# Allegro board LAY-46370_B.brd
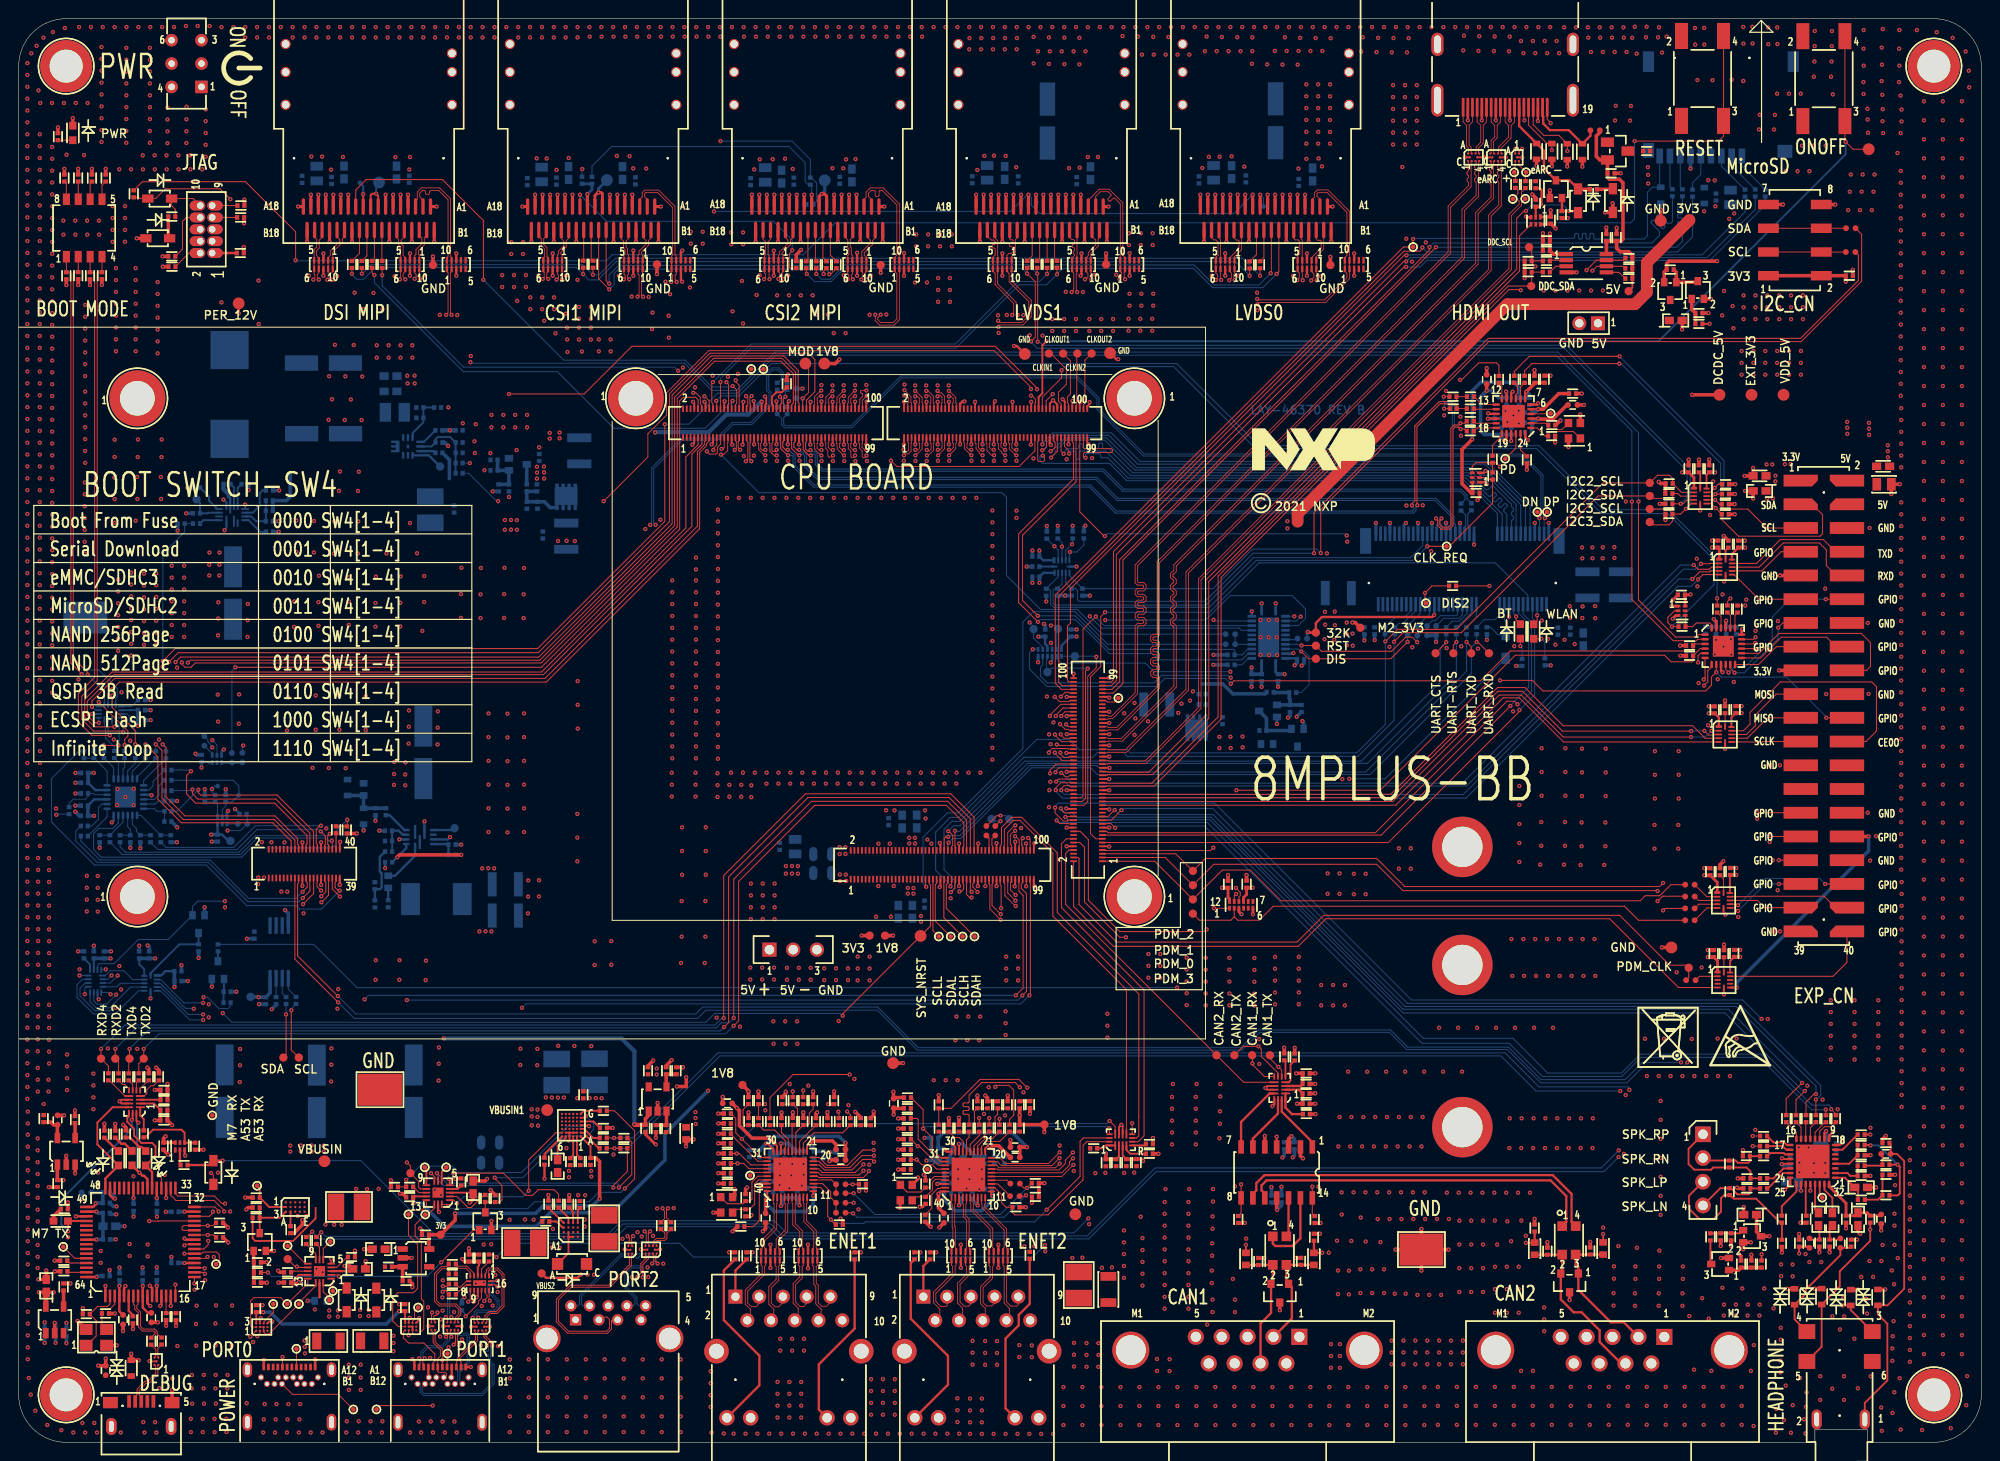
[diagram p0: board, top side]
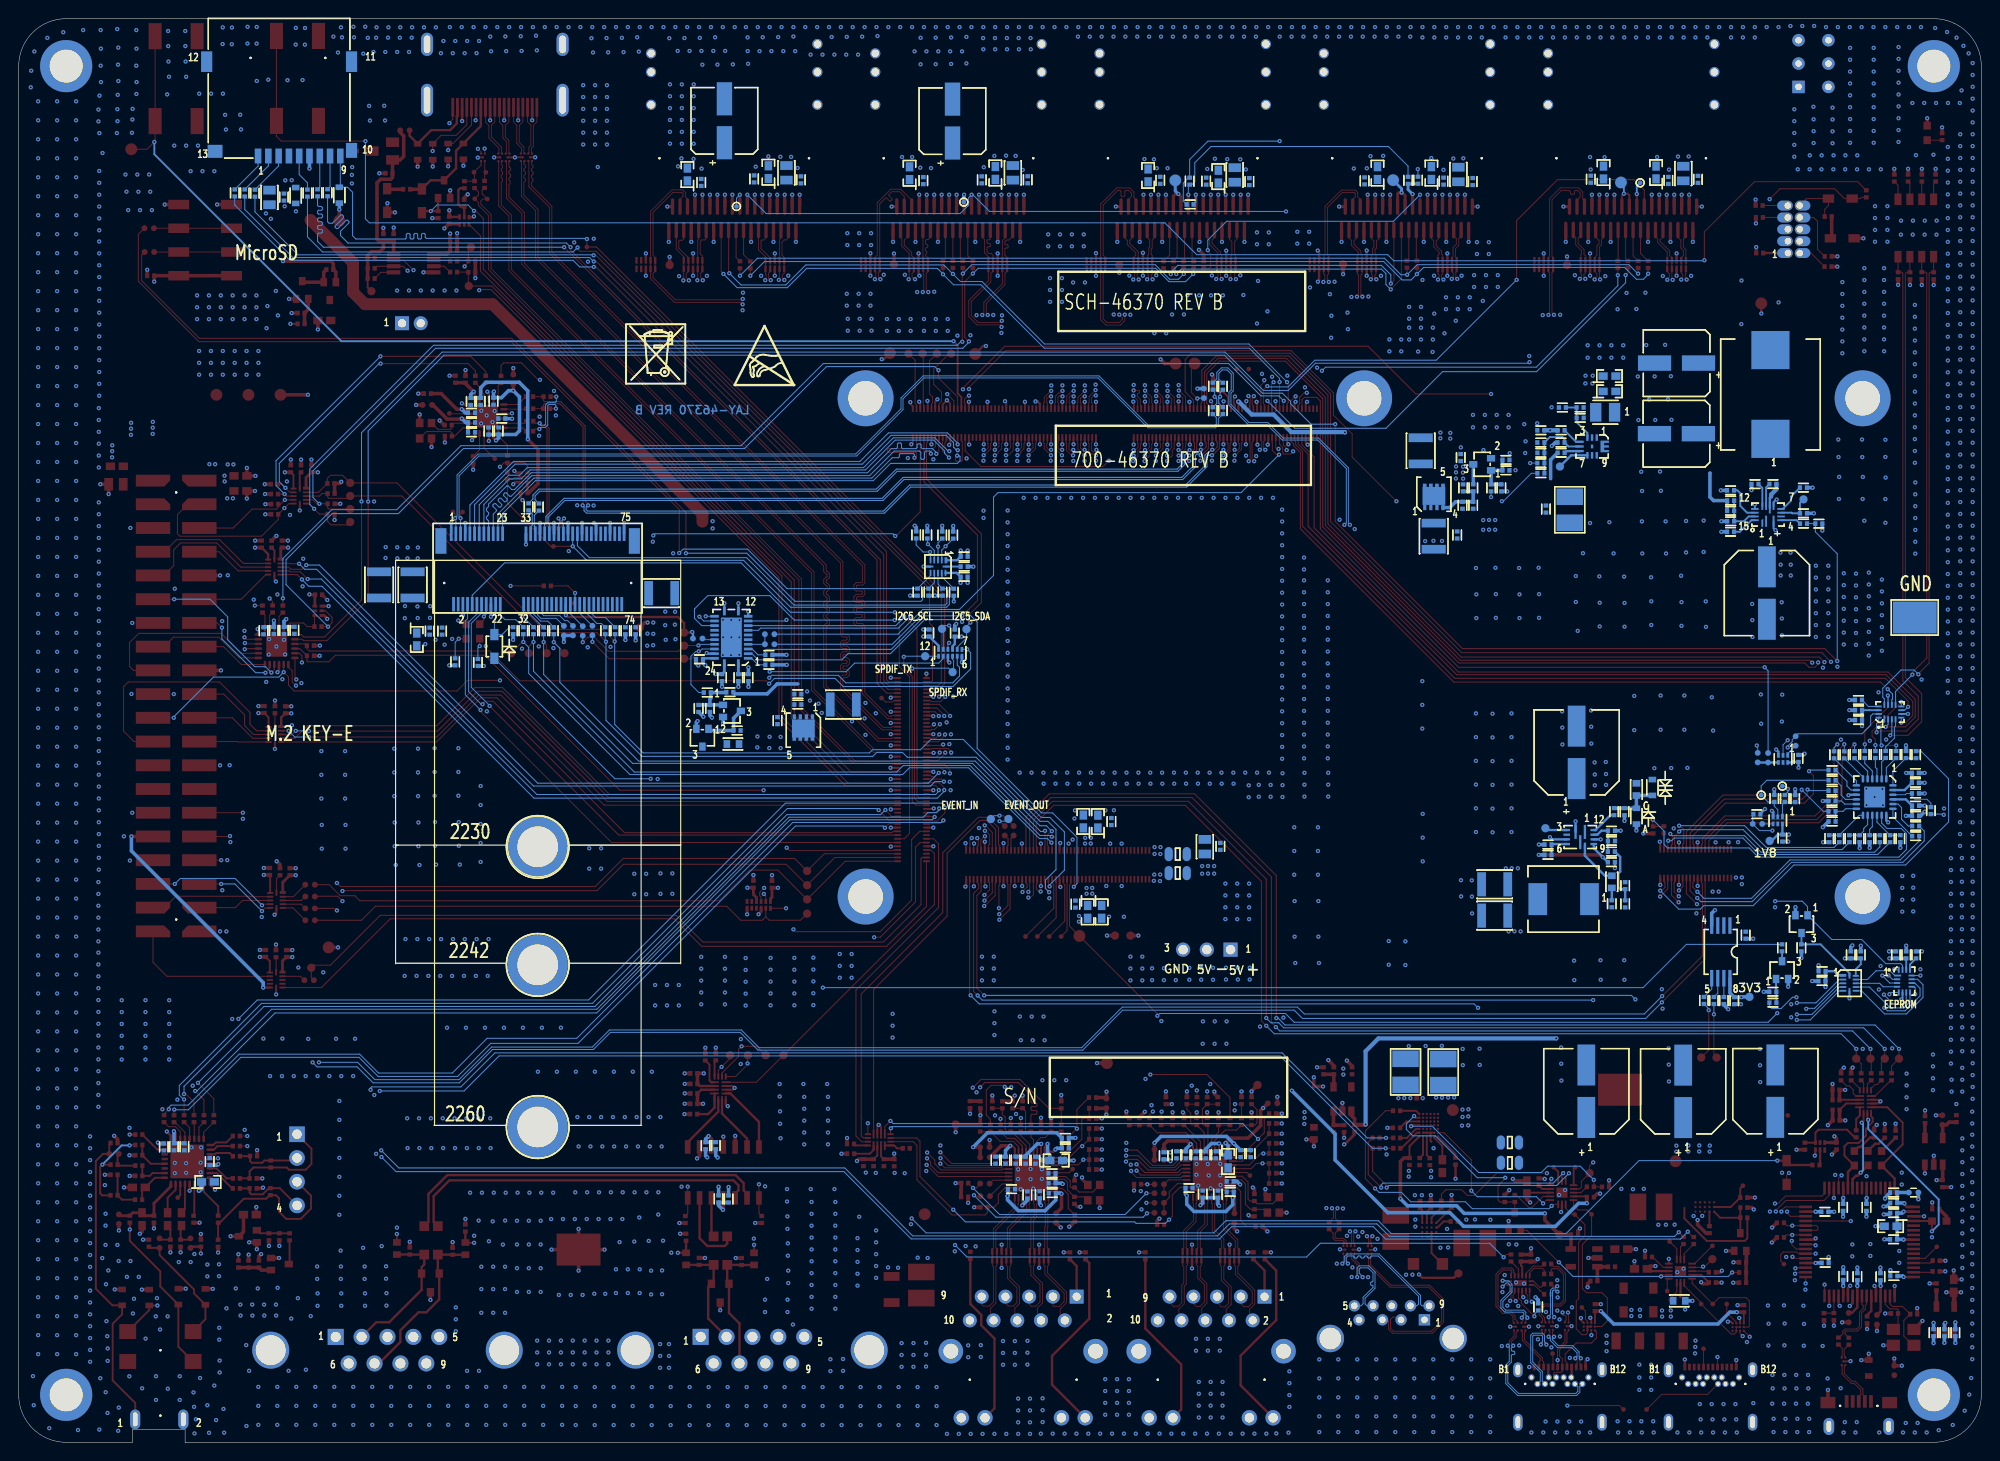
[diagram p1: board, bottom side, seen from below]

Outline 210 x 152.4 mm; copper layers: TOP, L2_GND1, L3_IN1, L4_POWER_1, L5_POWER_2, L6_IN2, L7_GND2, BOTTOM. Coordinates in mm from the lower left corner of the outline.
Outline path: 0,147.32 arc(1.49,150.91) 5.08,152.4 204.92,152.4 arc(208.51,150.91) 210,147.32 210,5.08 arc(208.51,1.49) 204.92,0 197.81,0 197.81,1.35 192.2,1.35 192.19,1.35 192.19,0.01 192.18,0 5.08,0 arc(1.49,1.49) 0,5.08 0,147.32

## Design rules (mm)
constraint set DEFAULT: min track width 0.109
net group AUD_PWR_EN: nets AUD_PWR_EN N108752409
net group DIFFPAIR0: nets USB_DBG_DN USB_DBG_DP
net group DIFFPAIR25: nets USB1_TXN USB1_TXP
net group DIFFPAIR26: nets USB1_RXN USB1_RXP
net group DIFFPAIR27: nets USB2_TXN USB2_TXP
net group DIFFPAIR28: nets USB2_RXN USB2_RXP
net group DIFFPAIR30: nets ST_FT_USB_DN ST_FT_USB_DP
net group DIFFPAIR31: nets FT_USB_DN FT_USB_DP
net group DIFFPAIR32: nets USB_HOST_DN USB_HOST_DP
net group DIFFPAIR33: nets USB_HOST_RXN USB_HOST_RXP
net group DIFFPAIR34: nets USB_HOST_TXN USB_HOST_TXP
net group DIFFPAIR35: nets USB1_DN_CN USB1_DP_CN
net group DIFFPAIR36: nets SSTXN2 SSTXP2
net group DIFFPAIR37: nets SSRXN2 SSRXP2
net group DIFFPAIR38: nets SSRXN1 SSRXP1
net group DIFFPAIR39: nets ETH1_TRX3_N ETH1_TRX3_P
net group DIFFPAIR40: nets ETH1_TRX2_N ETH1_TRX2_P
net group DIFFPAIR41: nets ETH1_TRX1_N ETH1_TRX1_P
net group DIFFPAIR42: nets ETH1_TRX0_N ETH1_TRX0_P
net group DIFFPAIR43: nets HDMI_TXN2_CN HDMI_TXP2_CN
net group DIFFPAIR44: nets HDMI_TXN1_CN HDMI_TXP1_CN
net group DIFFPAIR45: nets HDMI_TXN0_CN HDMI_TXP0_CN
net group DIFFPAIR46: nets HDMI_CLKN_CN HDMI_CLKP_CN
net group DIFFPAIR47: nets SS_RXN1 SS_RXP1
net group DIFFPAIR48: nets SS_RXN2 SS_RXP2
net group DIFFPAIR49: nets SS_TXN2 SS_TXP2
net group DIFFPAIR50: nets SS_TXN1 SS_TXP1
net group DIFFPAIR51: nets SSTXN1 SSTXP1
net group DIFFPAIR52: nets USB2_H_DN USB2_H_DP
net group DIFFPAIR53: nets USB2_H_TXN USB2_H_TXP
net group DIFFPAIR54: nets M2_USB_DN M2_USB_DP
net group DIFFPAIR55: nets EARC_N_HPD EARC_P_UTIL
net group DIFFPAIR56: nets CAN2H CAN2L
net group ENET1_MDIO: nets ENET1_MDIO ETH1_MDIO
net group ENET1_RD0: nets ENET1_RD0 ENET1_RXD0/RXDLY
net group ENET1_RD1: nets ENET1_RD1 ENET1_RXD1/TXDLY
net group ENET1_RD2: nets ENET1_RD2 ENET1_RXD2/PLLOFF
net group ENET1_RX_CTL: nets ENET1_RX_CTL ENET1_RXCTL/PHYAD2
net group ENET1_RXC: nets ENET1_RXC ENET1_RXC/PHYAD1
net group ETH1_MDC: nets ENET1_MDC ETH1_MDC
net group ETH_TRX0: nets ETH_TRX0_N ETH_TRX0_P
net group ETH_TRX1: nets ETH_TRX1_N ETH_TRX1_P
net group ETH_TRX2: nets ETH_TRX2_N ETH_TRX2_P
net group ETH_TRX3: nets ETH_TRX3_N ETH_TRX3_P
net group HP_MIC_P: nets HP_MIC_P N108750181
net group I2C2_SCL_3V3: nets I2C2_SCL_3V3 N104279466
net group I2C2_SDA_3V3: nets I2C2_SDA_3V3 N104279469
net group N108752359: nets N108752359 N108752379
net group PCIE_RX: nets PCIE_RXN PCIE_RXP
net group PCIE_TXN: nets N105095143 PCIE_TXN
net group PCIE_TXP: nets N105095140 PCIE_TXP
net group SPKOUTLN: nets SPK_LN SPKOUTLN
net group SPKOUTLP: nets SPK_LP SPKOUTLP
net group SPKOUTRN: nets SPK_RN SPKOUTRN
net group SPKOUTRP: nets SPK_RP SPKOUTRP
net group USB1_D: nets USB1_DN USB1_DP
net group USB2_D: nets USB2_DN USB2_DP
net group CAN1_H: nets CAN1_H CAN1_L N109066072
net group CAN2_H: nets CAN2_H CAN2_L N109088165
net group DSI: nets DSI_CKN DSI_CKP DSI_DN0 DSI_DN1 DSI_DN2 DSI_DN3 DSI_DP0 DSI_DP1 DSI_DP2 DSI_DP3
net group ETH1_DVDD3V3: nets ETH1_LED0/CFG_EXT
net group M-ENET1-TX: nets ENET1_TD0 ENET1_TD1 ENET1_TD2 ENET1_TD3 ENET1_TX_CTL ENET1_TXC
net group M-ENET-RX: nets ENET_RD0 ENET_RD1 ENET_RD2 ENET_RD3 ENET_RX_CTL ENET_RXC
net group M-ENET-TX: nets ENET_TD0 ENET_TD1 ENET_TD2 ENET_TD3 ENET_TX_CTL ENET_TXC
net group M-ENT1-RX: nets ENET1_RD3
net group M-HDMI: nets HDMI_TXCN HDMI_TXCP HDMI_TXN0 HDMI_TXN1 HDMI_TXN2 HDMI_TXP0 HDMI_TXP1 HDMI_TXP2
net group M-M2-SD: nets M2_SD_CLK M2_SD_CMD M2_SD_DATA0 M2_SD_DATA1 M2_SD_DATA2 M2_SD_DATA3 M2_SD_NRST M2_SD_WAKE_HOST
net group M-SD2: nets SD2_CLK SD2_CMD SD2_DATA0 SD2_DATA1 SD2_DATA2 SD2_DATA3
net group NCS_CLK: nets M2_PCM_CLK
net group NCS_POWER_PH: nets ILIM_5V_VBUS1 N101995244 N101995353 VCC_3V6 VLDO1_3V3 VTREF
net group PCIE_REQ: nets N101995643 N101995645 PCIE_REQ
net group REF_CLKN_CN: nets N101995453 PCIE_CLKN REF_CLKN_CN
net group REF_CLKP_CN: nets N101995404 N101995436 PCIE_CLKP REF_CLKP_CN

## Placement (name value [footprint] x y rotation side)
BH1  SMTSO-M25  [MH244-166T]  154.47 63.74 180 bottom
BH2  STANDOFF M2.5  [STANDOFF_CIRCLE_5P1-2P5MM_NSP]  66.04 111.76 0 top
BH3  STANDOFF M2.5  [STANDOFF_CIRCLE_5P1-2P5MM_NSP]  119.38 58.42 0 top
BH4  STANDOFF M2.5  [STANDOFF_CIRCLE_5P1-2P5MM_NSP]  119.38 111.76 0 top
BH5  .635" LONG  [SPACER_139T]  5.08 5.08 0 top
BH6  .635" LONG  [SPACER_139T]  204.92 147.32 0 top
BH7  .635" LONG  [SPACER_139T]  204.92 5.08 0 top
BH8  .635" LONG  [SPACER_139T]  5.08 147.32 0 top
BH9  SMTSO-M25  [MH244-166T]  154.47 51.1 180 bottom
BH10  SMTSO-M25  [MH244-166T]  154.47 33.74 180 bottom
BH11  STANDOFF M2.5  [STANDOFF_CIRCLE_5P1-2P5MM_NSP]  12.7 111.76 0 top
BH12  STANDOFF M2.5  [STANDOFF_CIRCLE_5P1-2P5MM_NSP]  12.7 58.42 0 top
C1  1.0UF  [0402_CC]  180.5 86.92 270 bottom
C2  0.1uF  [0402_CC]  181.61 86.91 270 bottom
C3  1.0UF  [0402_CC]  182.7 86.91 270 bottom
C4  0.1uF  [0402_CC]  183.8 86.88 270 bottom
C5  0.1uF  [0402_CC]  177.91 90.73 180 top
C6  1.0UF  [0402_CC]  131.92 81.86 270 bottom
C7  0.1uF  [0402_CC]  132.99 81.86 270 bottom
C8  1.0UF  [0402_CC]  134.75 81.86 270 bottom
C9  0.1uF  [0402_CC]  137.16 83.83 0 bottom
C10  0.1uF  [0402_CC]  178.68 104.22 90 top
C11  0.1uF  [0402_CC]  180.88 104.22 90 top
C12  0.1uF  [0402_CC]  108.84 94.83 180 bottom
C13  0.1uF  [0402_CC]  108.84 92.65 180 bottom
C14  1.0UF  [0402_CC]  86.12 30.77 270 bottom
C15  4.7uF  [CC0603]  185.26 24.37 180 top
C16  0.1uF  [0402_CC]  81.43 63.79 90 bottom
C17  22uF  [0805_CC]  83.08 63.76 90 bottom
C18  0.1uF  [0402_CC]  93.08 66.45 90 bottom
C19  22uF  [CC0603]  96.09 66.46 90 bottom
C20  22uF  [CC0603]  94.53 66.45 90 bottom
C21  0.1uF  [0402_CC]  96.93 57.61 270 bottom
C22  22uF  [CC0603]  94.12 56.78 270 bottom
C23  22uF  [CC0603]  95.62 56.78 270 bottom
C24  4.7uF  [CC1210]  35.34 25.2 0 top
C25  100uF  [CCE8P3X8P3]  31.9 37.57 90 bottom
C26  100uF  [CCE8P3X8P3]  22.04 37.59 90 bottom
C27  0.1uF  [0402_CC]  25.41 14.31 90 top
C29  2.2uF  [0402_CC]  35.61 19.84 180 top
C30  4.7uF  [CC0603]  36.43 18.56 0 top
C31  0.1uF  [0402_CC]  28.78 17.1 0 top
C32  0.1uF  [0402_CC]  67.34 39.78 90 top
C33  0.1uF  [0402_CC]  109.84 86.63 90 bottom
C34  1uF  [CC0603]  38.52 20.68 180 top
C35  2.2uF  [0402_CC]  43.53 22.23 180 top
C36  4.7uF  [CC1210]  57.57 39.63 90 bottom
C37  0.1uF  [0402_CC]  112.56 86.64 90 bottom
C40  100uF  [CCE8P3X8P3]  42.27 37.58 90 bottom
C41  47UF  [CC1210]  61.61 39.66 90 bottom
C42  0.1uF  [0402_CC]  60.42 37.2 90 top
C43  0.01UF  [0402_CC]  56.26 30.1 270 top
C44  1000pF  [0402_CC]  59.01 30.05 270 top
C45  0.1uF  [0402_CC]  41.34 14.42 90 top
C46  0.1uF  [0402_CC]  61.19 30.06 270 top
C47  4.7uF  [CC0603]  57.67 29.56 270 top
C48  0.1uF  [0402_CC]  46.41 16.94 0 top
C50  0.1uF  [0402_CC]  46.4 15.84 0 top
C51  2.2uF  [0402_CC]  47.35 27.87 270 top
C52  0.1uF  [0402_CC]  46.4 19.09 0 top
C53  0.1uF  [0402_CC]  46.4 18.02 0 top
C54  4.7uF  [CC0603]  48.62 27.29 90 top
C55  0.22uF  [0402_CC]  49.26 19.72 90 top
C56  2.2uF  [0402_CC]  48.18 19.72 90 top
C57  0.1uF  [0402_CC]  41.83 26.24 0 top
C59  0.1uF  [0402_CC]  69.79 23.2 90 top
C60  0.1uF  [0402_CC]  68.72 23.19 90 top
C61  47UF  [CC1210]  54.2 21.34 0 top
C62  47UF  [CC1210]  62.66 22.9 90 top
C64  1000pF  [0402_CC]  60.05 25.45 90 top
C65  0.1uF  [0402_CC]  102.07 26.48 90 bottom
C66  0.1uF  [0402_CC]  100.75 26.5 90 bottom
C67  0.1uF  [0402_CC]  99.42 27.74 0 bottom
C68  1.0UF  [0402_CC]  99.4 26.67 0 bottom
C69  0.1uF  [0402_CC]  103.77 27.1 180 bottom
C70  4.7uF  [CC0603]  98.99 30.17 180 bottom
C71  0.1uF  [0402_CC]  101.21 30.2 270 bottom
C72  4.7uF  [0402_CC]  102.26 30.2 270 bottom
C73  0.1uF  [0402_CC]  103.33 30.21 270 bottom
C74  0.1uF  [0402_CC]  104.41 30.21 270 bottom
C75  0.22uF  [0402_CC]  97.51 19.96 90 top
C76  4.7uF  [0402_CC]  98.02 32.59 180 bottom
C77  0.1uF  [0402_CC]  98.01 31.48 180 bottom
C78  1000pF  [CC1210]  113.42 16.84 270 top
C79  22PF  [0402_CC]  97.02 27.65 90 top
C80  22PF  [0402_CC]  97.03 25.9 270 top
C81  22PF  [0402_CC]  98.44 36.13 90 top
C82  470PF  [0402_CC]  95.09 33.59 180 top
C83  470PF  [0402_CC]  95.09 30.26 180 top
C84  1.0UF  [0402_CC]  80.37 27.93 0 bottom
C85  0.1uF  [0402_CC]  83.31 26.57 90 bottom
C86  0.1uF  [0402_CC]  81.68 26.56 90 bottom
C87  1.0UF  [0402_CC]  80.37 26.81 0 bottom
C88  0.1uF  [0402_CC]  84.78 27.22 180 bottom
C89  4.7uF  [CC0603]  80.59 30.07 270 bottom
C90  0.1uF  [0402_CC]  81.91 30.78 270 bottom
C91  4.7uF  [0402_CC]  82.98 30.77 270 bottom
C92  0.1uF  [0402_CC]  84.05 30.77 270 bottom
C93  0.1uF  [0402_CC]  85.1 30.77 270 bottom
C94  0.22uF  [0402_CC]  77.88 19.96 90 top
C95  4.7uF  [0402_CC]  78.18 30.9 270 bottom
C96  0.1uF  [0402_CC]  79.26 30.9 270 bottom
C97  22PF  [0402_CC]  77.78 26.2 90 top
C98  22PF  [0402_CC]  77.77 24.57 270 top
C99  22PF  [0402_CC]  79.16 36.58 90 top
C100  470PF  [0402_CC]  75.83 32 180 top
C101  470PF  [0402_CC]  75.83 29.86 180 top
C102  1.0UF  [0402_CC]  161.63 111.42 270 bottom
C103  0.01UF  [0402_CC]  160.57 111.43 270 bottom
C104  1.0UF  [0402_CC]  158.31 109.59 0 bottom
C105  0.01UF  [0402_CC]  161.54 108.12 180 bottom
C106  0.01UF  [0402_CC]  161.54 109.17 180 bottom
C107  1.0UF  [0402_CC]  159.73 108.25 90 bottom
C108  0.01UF  [0402_CC]  159.2 111.46 270 bottom
C109  0.01UF  [0402_CC]  158.65 108.26 90 bottom
C110  18PF  [0402_CC]  164.03 107.71 0 top
C111  18PF  [0402_CC]  164.04 108.9 0 top
C112  0.1uF  [0402_CC]  143.99 86.88 270 bottom
C113  0.1uF  [0402_CC]  145.08 86.88 270 bottom
C114  0.1uF  [0402_CC]  164.7 86.84 270 bottom
C115  0.1uF  [0402_CC]  166.02 86.84 270 bottom
C116  10uF  [CC0603]  167.41 85.95 270 bottom
C117  100UF  [1210_CC]  171.44 91.79 90 bottom
C118  100UF  [1210_CC]  141.2 90.9 180 bottom
C119  100UF  [1210_CC]  167.86 91.79 90 bottom
C120  0.1uF  [0402_CC]  155.44 100.14 270 bottom
C121  0.1uF  [0402_CC]  154.33 100.12 270 bottom
C123  47uF  [0805_CC]  183.17 133.26 270 bottom
C124  0.1uF  [0402_CC]  181.62 133.3 270 bottom
C125  10uF  [CC0603]  64.61 135.87 90 bottom
C126  0.1uF  [0402_CC]  65.99 135.04 90 bottom
C127  22uF  [CC0603]  58.84 135.88 90 bottom
C128  0.1uF  [0402_CC]  57.54 135.01 90 bottom
C129  22uF  [0805_CC]  55.95 135.72 90 bottom
C130  0.1uF  [0402_CC]  54.42 134.96 90 bottom
C131  10uF  [CC0603]  89.15 135.62 90 bottom
C132  0.1uF  [0402_CC]  87.86 135.1 90 bottom
C133  22uF  [CC0603]  81.64 135.49 90 bottom
C134  0.1uF  [0402_CC]  82.94 135 90 bottom
C135  22uF  [0805_CC]  79.88 135.67 90 bottom
C136  0.1uF  [0402_CC]  78.32 134.96 90 bottom
C137  10uF  [CC0603]  40.43 135.93 90 bottom
C138  0.1uF  [0402_CC]  41.79 135.22 90 bottom
C139  22uF  [CC0603]  34.81 135.93 90 bottom
C140  0.1uF  [0402_CC]  33.48 135.08 90 bottom
C141  22uF  [0805_CC]  31.89 135.82 90 bottom
C142  0.1uF  [0402_CC]  30.32 135.2 90 bottom
C143  0.1uF  [0402_CC]  136.97 134.87 90 bottom
C144  22uF  [CC0603]  129.78 135.97 90 bottom
C145  0.1uF  [0402_CC]  126.3 135.15 90 bottom
C146  100uF  [CCE6P8X6P8]  134.49 141.47 90 bottom
C147  22uF  [CC0603]  114.68 135.86 90 bottom
C148  0.1uF  [0402_CC]  113.21 135.06 90 bottom
C149  0.1uF  [0402_CC]  106.95 135.15 90 bottom
C150  22uF  [0805_CC]  103.62 135.9 90 bottom
C151  100uF  [CCE6P8X6P8]  110.08 141.44 90 bottom
C152  10uF  [CC0603]  138.45 135.72 90 bottom
C153  0.1uF  [0402_CC]  131.31 135.25 90 bottom
C154  22uF  [0805_CC]  127.85 135.9 90 bottom
C155  22uF  [CC0603]  105.5 135.88 90 bottom
C156  0.1uF  [0402_CC]  102.04 135.16 90 bottom
C157  1uF  [0402_CC]  174.19 138.23 0 top
C158  1uF  [0402_CC]  170.38 135.85 0 top
C161  1uF  [0402_CC]  160.15 134.66 90 top
C162  1uF  [0402_CC]  161.22 134.64 90 top
C163  0.22uF  [0402_CC]  25.54 17.09 0 top
C164  0.22uF  [0402_CC]  25.41 25.12 180 top
C168  1.0UF  [0402_CC]  163.46 127.56 180 top
C169  0.1uF  [0402_CC]  163.47 128.66 180 top
C170  1uF  [0402_CC]  169.88 128.97 90 top
C171  0.1uF  [0402_CC]  170.98 128.97 90 top
C174  4.7uF  [CC0603]  197.14 27.28 0 top
C175  4.7uF  [0402_CC]  191.28 23.89 270 top
C176  220PF  [0402_CC]  196.06 21.32 270 top
C177  22uF  [CC0603]  194.07 23.89 270 top
C178  22uF  [CC0603]  192.58 23.89 270 top
C179  220PF  [0402_CC]  190.51 21.32 90 top
C181  15PF  [0402_CC]  197.14 30.73 180 top
C182  0.1uF  [0402_CC]  199.8 28.64 0 top
C183  0.1uF  [0402_CC]  197.14 31.83 0 top
C184  4.7uF  [0402_CC]  194.47 31.62 270 bottom
C185  0.1uF  [0402_CC]  193.38 31.64 270 bottom
C186  0.1uF  [0402_CC]  192.27 31.64 270 bottom
C187  4.7uF  [CC0603]  189.75 27.87 180 bottom
C188  0.1uF  [0402_CC]  189.56 30.05 90 bottom
C189  10uF  [CC0603]  196.8 23.89 270 top
C190  0.1uF  [0402_CC]  195.53 23.89 270 top
C191  0.1uF  [0402_CC]  197.14 29.62 0 top
C192  15PF  [0402_CC]  197.14 28.52 0 top
C193  15PF  [0402_CC]  199.8 32.04 180 top
C194  15PF  [0402_CC]  184.92 28.25 0 top
C195  15PF  [0402_CC]  183.02 29.79 90 top
C196  15PF  [0402_CC]  184.87 30.64 180 top
C197  0.22uF  [0402_CC]  183.23 22 90 top
C198  15PF  [0402_CC]  188.66 21.3 90 top
C199  15PF  [0402_CC]  183.07 26.83 90 top
C200  0.1uF  [0402_CC]  184.29 19.08 90 top
C201  15PF  [0402_CC]  184.92 27.18 180 top
C202  0.1uF  [0402_CC]  136.5 31.75 270 bottom
C203  1.0UF  [0402_CC]  135.41 31.76 270 bottom
C204  1.0UF  [0402_CC]  134.04 26.04 90 bottom
C205  0.1uF  [0402_CC]  135.11 26.05 90 bottom
C206  56PF  [0402_CC]  132.64 19.35 270 top
C207  0.01UF  [0402_CC]  138.59 21.95 90 top
C208  56PF  [0402_CC]  137.2 19.37 90 top
C214  56PF  [0402_CC]  163.57 20.45 270 top
C215  0.01UF  [0402_CC]  162.2 22.94 90 top
C216  56PF  [0402_CC]  168.15 20.48 90 top
C217  1.0UF  [0402_CC]  137.75 38.37 0 top
C218  0.01UF  [0402_CC]  137.76 39.49 180 top
C219  1.0UF  [0402_CC]  137.75 37.34 0 top
C220  0.01UF  [0402_CC]  137.76 36.24 180 top
C223  1.0UF  [0402_CC]  195.87 124.89 180 top
C224  22uF  [CC0603]  186.28 101.84 180 top
C226  22uF  [0805_CC]  199.59 102.56 0 top
C228  0.1uF  [0402_CC]  181.47 78.41 90 top
C229  0.1uF  [0402_CC]  183.71 78.44 90 top
C230  0.1uF  [0402_CC]  181.83 96.16 90 top
C231  0.1uF  [0402_CC]  184 96.15 90 top
C232  0.1uF  [0402_CC]  180.99 61.08 90 top
C233  0.1uF  [0402_CC]  183.14 61.11 90 top
C234  0.1uF  [0402_CC]  181.36 52.32 90 top
C235  0.1uF  [0402_CC]  183.56 52.33 90 top
C236  1uF  [0402_CC]  3.95 11.74 90 bottom
C237  0.1uF  [0402_CC]  5.11 11.74 90 bottom
C238  1.0UF  [0402_CC]  2.78 11.74 90 bottom
C239  4.7uF  [CC0603]  2.95 16.75 90 top
C240  0.22uF  [0402_CC]  4.8 16.63 90 top
C241  0.1uF  [0402_CC]  13.26 17.73 90 bottom
C242  0.1uF  [0402_CC]  10.79 17.72 90 bottom
C243  4.7uF  [CC0603]  9.7 23.14 0 bottom
C244  0.1uF  [0402_CC]  16.71 19.21 180 bottom
C245  0.1uF  [0402_CC]  12.29 25.15 270 bottom
C246  0.1uF  [0402_CC]  16.74 24.68 180 bottom
C251  0.1uF  [0402_CC]  15.77 13.46 270 top
C252  27 PF  [0402_CC]  7.23 13.72 180 top
C253  27 PF  [0402_CC]  9.28 13.79 0 top
C254  0.22uF  [0402_CC]  39.54 57.65 270 bottom
C255  100uF  [CCE8P3X8P3]  43.3 73.86 90 bottom
C256  220PF  [0402_CC]  38.11 59.59 90 bottom
C257  0.1uF  [0402_CC]  56.08 97.13 270 bottom
C258  100UF  [1210_CC]  52.07 56.38 0 bottom
C259  100UF  [1210_CC]  52.07 59.74 0 bottom
C260  100UF  [1210_CC]  58.59 97 270 bottom
C261  0.01UF  [0402_CC]  55.45 102.17 270 bottom
C263  1.0UF  [0402_CC]  39.58 62.1 180 bottom
C264  0.22uF  [0402_CC]  55.51 100.31 90 bottom
C265  0.22uF  [0402_CC]  38.18 67.51 270 bottom
C266  1uF  [0402_CC]  55.7 105.42 90 bottom
C267  100UF  [1210_CC]  59.99 106.14 90 bottom
C269  0.1uF  [0402_CC]  50.86 104.05 180 bottom
C270  47UF  [CC1210]  44.04 99.83 270 bottom
C271  0.1uF  [0402_CC]  46.59 99.9 270 bottom
C272  1000pF  [0402_CC]  42.93 110.78 0 bottom
C273  22uF  [CC0603]  39.79 114.14 180 bottom
C274  22uF  [CC0603]  39.79 112.5 180 bottom
C275  0.1uF  [0402_CC]  47.13 108.34 0 bottom
C276  1000pF  [0402_CC]  44.97 108.33 0 bottom
C277  0.22uF  [0402_CC]  47.13 105.92 0 bottom
C278  0.22uF  [0402_CC]  22.3 102.58 180 bottom
C279  100uF  [CCE8P3X8P3]  22.94 90.91 270 bottom
C280  5.6PF  [0402_CC]  26.82 100.81 180 bottom
C281  100uF  [CCE6P8X6P8]  32.61 115.53 0 bottom
C282  100uF  [CCE6P8X6P8]  32.62 107.97 0 bottom
C283  1.0UF  [0402_CC]  24.22 102.57 180 bottom
C286  1.0UF  [0402_CC]  118.52 29.94 270 top
C287  0.1uF  [0402_CC]  119.61 29.94 270 top
C288  1.0UF  [0402_CC]  116.32 29.93 270 top
C289  0.1uF  [0402_CC]  117.42 29.93 270 top
C294  0.1uF  [0402_CC]  9.38 25.62 0 bottom
C295  4.7uF  [0402_CC]  9.38 26.74 0 bottom
C296  0.1uF  [0402_CC]  9.39 21.72 0 bottom
C297  0.1uF  [0402_CC]  9.37 24.54 0 bottom
C298  4.7uF  [0402_CC]  9.36 17.8 0 bottom
C299  0.1uF  [0402_CC]  14.77 17.76 90 bottom
C300  0.1uF  [0402_CC]  14.79 25.15 270 bottom
C305  1.0UF  [0402_CC]  13.97 52.18 90 bottom
C306  0.01UF  [0402_CC]  12.9 52.18 270 bottom
C307  1.0UF  [0402_CC]  17.04 50.43 0 bottom
C308  0.01UF  [0402_CC]  17.05 49.38 180 bottom
C309  1.0UF  [0402_CC]  8.04 52.18 90 bottom
C310  0.01UF  [0402_CC]  9.13 52.18 270 bottom
C317  1.0UF  [0402_CC]  7.05 70.6 180 bottom
C318  0.1uF  [0402_CC]  7.05 71.66 180 bottom
C319  1.0UF  [0402_CC]  7.03 68.16 180 bottom
C320  0.1uF  [0402_CC]  7.03 67.06 180 bottom
C321  1.0UF  [0402_CC]  13.14 78.38 0 bottom
C322  0.01UF  [0402_CC]  13.14 77.31 180 bottom
C324  1.0UF  [0402_CC]  4.15 27.69 270 top
C325  4.7uF  [0402_CC]  2.67 34.65 90 top
C326  0.22uF  [0402_CC]  6.02 34.54 90 top
C327  0.1uF  [0402_CC]  21.29 64.68 270 bottom
C328  1.0UF  [0402_CC]  15.55 36.64 0 top
C329  0.1uF  [0402_CC]  15.55 37.72 0 top
C330  1.0UF  [0402_CC]  15.54 35.58 0 top
C331  0.1uF  [0402_CC]  15.54 34.46 0 top
C332  0.01UF  [0402_CC]  26.83 101.91 180 bottom
C333  1.0UF  [0402_CC]  99.44 28.8 0 bottom
C334  1.0UF  [0402_CC]  105.48 30.2 270 bottom
C335  0.1uF  [0402_CC]  19.57 73.21 90 bottom
C336  0.1uF  [0402_CC]  131.38 59.75 90 top
C337  0.1uF  [0402_CC]  129.4 59.73 90 top
C338  0.1uF  [0402_CC]  26.44 47.27 270 bottom
C339  0.1uF  [0402_CC]  87.48 30.67 90 bottom
C340  0.22uF  [0402_CC]  126.63 78.98 0 bottom
C341  0.01UF  [0402_CC]  128.81 77.25 270 bottom
C342  100UF  [1210_CC]  121.77 78.98 180 bottom
C343  0.1uF  [0402_CC]  137.25 78.56 270 bottom
C345  0.1uF  [0402_CC]  163.92 130.83 90 top
C346  0.1uF  [0402_CC]  15.5 31.71 270 top
C348  4.7uF  [CC0603]  177.3 120.09 0 top
C349  0.1uF  [0402_CC]  155.94 101.63 0 top
CON1  HDR 1X4  [HDR104]  180.22 32.98 0 top
D2  BAT54HT1  [SOD323]  35.09 15.24 180 top
D4  BAT54HT1  [SOD323]  38.27 15.23 180 top
D5  MBR140SFT  [SOD123LF]  59.21 19.09 180 top
D6  NSR0320  [SOD323]  159.1 85.2 0 bottom
D9  BAT54HT1  [SOD323]  170.57 132.93 180 top
D10  ESD5B5.0ST1G  [DIODE2_SOD523]  167.31 138.16 270 top
D11  ESD5B5.0ST1G  [DIODE2_SOD523]  165.7 138.16 270 top
D12  ESD5B5.0ST1G  [DIODE2_SOD523]  164.05 138.19 270 top
D13  ESD5B5.0ST1G  [DIODE2_SOD523]  162.42 138.19 270 top
D14  PESD2IVN24-T  [SOT23_A]  134.94 15.97 180 top
D15  PESD2IVN24-T  [SOT23_A]  165.95 17.07 180 top
D16  LED_ORANGE  [LED_0603_11MIL]  13.59 30.4 270 top
D17  LED GREEN  [LED_0603]  12.13 30.42 270 top
D20  LED_ORANGE  [LED_0603_11MIL]  10.67 30.41 270 top
D21  LED GREEN  [LED_0603]  4.5 23.68 0 top
D22  NSR0320  [SOD323]  14.88 128.89 90 top
D23  NSR0320  [SOD323]  15.09 133.14 90 top
D24  BZX585-B3V3  [SOD523]  36.9 67.03 270 bottom
D25  LED RED  [LED_0603]  5.79 140.17 90 top
D26  NSR0320  [SOD323]  20.83 28.88 0 top
D30  LED GREEN  [LED_0603]  162.11 86.8 90 top
D31  LED_ORANGE  [LED_0603_11MIL]  160.67 86.81 90 top
D32  BAT54HT1  [SOD323]  166.85 132.9 180 top
F1  7A  [FUSE_3P4X1P8]  33.15 10.84 0 top
F2  7A  [FUSE_3P4X1P8]  37.83 10.86 180 top
J1  DF40C-100DS-0.4V(51)  [CON100_0P4_22P8X3P1_SM]  80.89 109.11 0 top
J2  DF40C-100DS-0.4V(51)  [CON100_0P4_22P8X3P1_SM]  104.53 109.11 0 top
J3  DF40C-100DS-0.4V(51)  [CON100_0P4_22P8X3P1_SM]  98.82 61.82 0 top
J4  DF40C-100DS-0.4V(51)  [CON100_0P4_22P8X3P1_SM]  114.41 72 90 top
J5  23K20101#LCP-582RF  [CON24_USB_TYPEC_RA_SMT_TH]  32.02 6.95 0 top
J6  23K20101#LCP-582RF  [CON24_USB_TYPEC_RA_SMT_TH]  48.13 6.95 0 top
J7  USB_TYPE_A  [CON9_USB_16P8X14P2_TH]  59.58 13.11 90 top
J8  RJ-45  [CON_RJ45_10_2LED_TH]  96.8 15.59 180 top
J9  RJ-45  [CON_RJ45_10_2LED_TH]  76.69 15.59 180 top
J10  CON_MINI CARD_RA  [CON_75_0P5_22X9_RA]  154.47 93.66 180 bottom
J11  CONN_SD_CARD 9  [CON9_SDCARD_1P1MM]  182.14 144.95 0 bottom
J12  CON 2X18  [CON2X18_RECEP_WSHELL_0P8_SM_RA]  61.46 141.44 180 top
J13  CON 2X18  [CON2X18_RECEP_WSHELL_0P8_SM_RA]  85.45 141.44 180 top
J14  CON 2X18  [CON2X18_RECEP_WSHELL_0P8_SM_RA]  37.46 141.44 180 top
J15  CON 2X18  [CON2X18_RECEP_WSHELL_0P8_SM_RA]  133.44 141.44 180 top
J16  CON 2X18  [CON2X18_RECEP_WSHELL_0P8_SM_RA]  109.44 141.44 180 top
J17  CON HDMI 1X19  [CON_RA_HDMI_19P_0P5_SM_B]  159.06 148.13 180 top
J18  KJ366EYS  [CON6_AUDIOJACK_RA_TH]  197.53 2.46 90 top
J19  DB9  [CON_DB_9F_109_TH_RA]  137.03 11.29 0 top
J20  DB9  [CON_DB_9F_109_TH_RA]  176.08 11.28 0 top
J21  TSM-120-01-F-DV-A  [HDR220_TSM_A_SM]  193.15 78.83 0 top
J22  SSM-104-L-DV  [CON_2X4_SKT_100_SM]  190.05 128.69 180 top
J23  USB205FB-C1013223  [CON_USB_TYPE_B_SM_A]  13.11 1.75 0 top
J24  HDR 2X5  [CON_2RH_10_50]  20.7 127.31 90 top
J25  DF40C-40DS-0.4V(51)  [CON40_0P4_10P8X3P08_SM]  30.55 61.95 0 top
J26  HDR 1X3  [HDR103]  80.33 52.74 90 top
J27  HDR 1X2  [HDR102_TMM]  168.99 119.8 0 top
L1  120 Ohm  [IND_0402]  93.62 36.29 270 top
L2  120 Ohm  [IND_0402]  98.99 24 90 top
L3  120 Ohm  [IND_0402]  106.62 31.59 180 top
L4  120 Ohm  [IND_0402]  106.61 30.51 180 top
L5  120 Ohm  [IND_0402]  75.83 36.29 0 top
L6  120 Ohm  [IND_0402]  79.92 24.01 90 top
L7  120 Ohm  [IND_0402]  87.96 30.22 180 top
L8  120 Ohm  [IND_0402]  87.96 31.36 180 top
L9  120 Ohm  [IND_0402]  166.28 111.06 0 top
L10  120 Ohm  [IND_0402]  157.08 113.79 270 top
L11  120 Ohm  [IND_0402]  194.92 21.32 270 top
L12  120 Ohm  [IND_0402]  191.62 21.32 270 top
L13  120 Ohm  [IND_0402]  199.8 30.88 0 top
L14  120 Ohm  [IND_0402]  199.28 23.89 90 top
L15  120 Ohm  [IND_0402]  9.31 7.69 90 top
L16  1.5uH  [IND_IHLP]  44.72 58.15 0 bottom
L17  0.47uH  [IND_SPH2520]  40.25 110.26 0 bottom
L18  10uH  [IND2_11P5X10P3_SM]  22.57 112.17 180 bottom
L19  100uH  [IND4_AMCW3225_SMT]  134.92 20.52 270 top
L20  100uH  [IND4_AMCW3225_SMT]  165.88 21.62 270 top
L21  120 Ohm  [IND_0402]  14.19 13.35 90 top
L22  120 Ohm  [IND_0402]  11.17 13.12 90 top
L23  120 Ohm  [IND_0402]  4.16 34.5 90 top
L24  120 Ohm  [IND_0402]  7.24 26.74 0 bottom
L25  120 OHM  [IND_0603]  186.27 103.46 0 top
L26  120 OHM  [IND_0603]  199.49 104.49 180 top
NOREF  -  []  144.12 96.49 0 top
NOREF#2  -  []  194.57 29.62 0 top
NOREF#3  -  []  14.75 8.06 90 top
NOREF#4  -  []  102.44 132.29 90 top
NOREF#5  -  []  48.32 16.28 0 top
NOREF#6  -  []  174.39 138.3 0 top
NOREF#7  -  []  43.62 27.53 0 top
NOREF#8  -  []  13.05 35.72 0 top
NOREF#9  -  []  116.72 31.78 90 top
NOREF#10  -  []  183.35 48.44 90 top
NOREF#11  -  []  44.36 12.43 90 top
NOREF#12  -  []  53.46 137.47 90 top
NOREF#13  -  []  93.45 137.47 90 top
NOREF#14  -  []  45.83 12.83 0 top
NOREF#15  -  []  41.46 64.04 0 top
NOREF#16  -  []  191.48 0.21 90 top
NOREF#17  -  []  174.74 148.91 0 top
NOREF#18  -  []  57.38 103.18 0 top
NOREF#19  -  []  -375.95 -299.55 0 top
NOREF#20  -  []  119.41 140.8 0 top
NOREF#21  -  []  47.24 13.04 0 top
NOREF#22  -  []  89.39 86.34 0 top
NOREF#23  -  []  14.33 9.28 0 top
NOREF#24  -  []  154.55 142.91 0 top
NOREF#25  -  []  46.63 12.03 0 top
NOREF#26  -  []  78.85 129.78 90 top
NOREF#27  -  []  181.78 48.69 0 top
NOREF#28  -  []  16.22 116.72 0 top
NOREF#29  -  []  30.94 18.72 90 top
NOREF#30  -  []  117.44 137.47 90 top
NOREF#31  -  []  72.42 153.05 0 top
NOREF#32  -  []  135.54 83.93 90 top
NOREF#33  -  []  16.31 1.7 90 top
NOREF#34  -  []  87.42 60.25 0 top
NOREF#35  -  []  29.46 137.47 90 top
NOREF#36  -  []  110.58 96.45 0 top
NOREF#37  -  []  115.95 63 90 top
NOREF#38  -  []  67.66 129.78 0 top
NOREF#39  -  []  12.6 35.26 0 top
NOREF#40  -  []  181.74 92.64 0 top
NOREF#41  -  []  95.41 140.8 0 top
NOREF#42  -  []  21.43 99.51 90 top
NOREF#43  -  []  49.6 11.98 0 top
NOREF#44  -  []  126.44 132.29 90 top
NOREF#45  -  []  9.81 4.25 90 top
NOREF#46  -  []  90.69 107.57 90 top
NOREF#47  -  []  191.33 11.86 0 top
NOREF#48  -  []  163.47 89.71 90 top
NOREF#49  -  []  45.46 137.47 90 top
NOREF#50  -  []  43 106.11 90 top
NOREF#51  -  []  48.1 16.22 0 top
NOREF#52  -  []  191.48 13.06 0 top
NOREF#53  -  []  134.49 83.38 90 top
NOREF#54  -  []  67.36 127.27 90 top
NOREF#55  -  []  13.21 48.09 90 top
NOREF#56  -  []  116.04 132.29 0 top
NOREF#57  -  []  179.25 100.49 0 top
NOREF#58  -  []  44.16 12.83 0 top
NOREF#59  -  []  141.44 137.47 90 top
NOREF#60  -  []  48.32 16.28 90 top
NOREF#61  -  []  183.31 94.09 90 top
NOREF#62  -  []  126.29 76.24 0 top
NOREF#63  -  []  54.46 132.29 0 top
NOREF#64  -  []  91.35 127.27 90 top
NOREF#65  -  []  25.15 60.41 0 top
NOREF#66  -  []  114.51 74.79 0 top
NOREF#67  -  []  183.31 92.89 90 top
NOREF#68  -  []  13.02 36.67 90 top
NOREF#69  -  []  40.1 107.66 0 top
NOREF#70  -  []  108.62 60.28 90 top
NOREF#71  -  []  22.57 107.42 90 top
NOREF#72  -  []  44.47 27.98 0 top
NOREF#73  -  []  29.46 137.47 0 top
NOREF#74  -  []  181.69 74.72 0 top
NOREF#75  -  []  43.52 28.08 0 top
NOREF#76  -  []  53.46 137.47 90 top
NOREF#77  -  []  57.6 100.06 0 top
NOREF#78  -  []  71.89 107.57 0 top
NOREF#79  -  []  78.85 129.78 90 top
NOREF#80  -  []  151.81 149.65 0 top
NOREF#81  -  []  77.45 137.47 90 top
NOREF#82  -  []  126.84 129.78 90 top
NOREF#83  -  []  115.64 129.78 0 top
NOREF#84  -  []  133.57 18.82 90 top
NOREF#85  -  []  38.04 -25.29 0 top
NOREF#86  -  []  158.89 136.94 90 top
NOREF#87  -  []  110.22 60.25 90 top
NOREF#88  -  []  78.45 132.29 90 top
NOREF#89  -  []  77.45 137.47 0 top
NOREF#90  -  []  164.47 91.99 90 top
NOREF#91  -  []  93.13 107.54 0 top
NOREF#92  -  []  92.05 132.29 0 top
NOREF#93  -  []  30.59 24.69 90 top
NOREF#94  -  []  15.63 112.61 0 top
NOREF#95  -  []  41.46 64.04 90 top
NOREF#96  -  []  139.34 127.27 90 top
NOREF#97  -  []  157.27 136.94 0 top
NOREF#98  -  []  30.94 19.12 0 top
NOREF#99  -  []  77.45 137.47 90 top
NOREF#100  -  []  145.22 97.26 0 top
NOREF#101  -  []  16.31 1.7 90 top
NOREF#102  -  []  101.44 137.47 90 top
NOREF#103  -  []  126.29 76.24 0 top
NOREF#104  -  []  174.39 147.8 0 top
NOREF#105  -  []  163.33 127.27 90 top
NOREF#106  -  []  59.33 23.5 0 top
NOREF#107  -  []  69.49 107.54 0 top
NOREF#108  -  []  191.33 11.86 0 top
NOREF#109  -  []  102.84 129.78 90 top
NOREF#110  -  []  183.26 74.97 90 top
NOREF#111  -  []  135.54 83.93 90 top
NOREF#112  -  []  54.86 129.78 90 top
NOREF#113  -  []  13 35.26 90 top
NOREF#114  -  []  154.97 89.71 0 top
NOREF#115  -  []  194.83 9.86 0 top
NOREF#116  -  []  -54.64 134.03 0 top
NOREF#117  -  []  92.29 107.54 90 top
NOREF#118  -  []  175.59 137.7 90 top
NOREF#119  -  []  27.72 106.42 90 top
NOREF#120  -  []  125.06 77.66 0 top
NOREF#121  -  []  135.54 36.73 90 top
NOREF#122  -  []  30.86 129.78 90 top
NOREF#123  -  []  125.44 137.47 90 top
NOREF#124  -  []  58.13 34.75 90 top
NOREF#125  -  []  67.36 127.27 90 top
NOREF#126  -  []  181.75 57.21 0 top
NOREF#127  -  []  68.97 112.61 0 top
NOREF#128  -  []  180.6 100.49 90 top
NOREF#129  -  []  45.46 137.47 90 top
NOREF#130  -  []  179.72 54.86 90 top
NOREF#131  -  []  102.84 129.78 0 top
NOREF#132  -  []  45.46 137.47 90 top
NOREF#133  -  []  125.44 137.47 0 top
NOREF#134  -  []  124.39 74.59 0 top
NOREF#135  -  []  144.4 153.05 0 top
NOREF#136  -  []  9.81 4.25 0 top
NOREF#137  -  []  183.13 49.89 90 top
NOREF#138  -  []  30.86 129.78 90 top
NOREF#139  -  []  101.82 18.59 90 top
NOREF#140  -  []  134.19 19 90 top
NOREF#141  -  []  29.46 137.47 90 top
NOREF#142  -  []  115.34 127.27 90 top
NOREF#143  -  []  69.46 137.47 90 top
NOREF#144  -  []  117.33 31.76 90 top
NOREF#145  -  []  89.02 60.28 0 top
NOREF#146  -  []  159.92 136.95 0 top
NOREF#147  -  []  -120.2 -208.23 0 top
NOREF#148  -  []  48.43 153.05 0 top
NOREF#149  -  []  134.32 37.34 0 top
NOREF#150  -  []  77.45 137.47 90 top
NOREF#151  -  []  140.04 132.29 0 top
NOREF#152  -  []  143.4 140.8 0 top
NOREF#153  -  []  174.74 137.65 0 top
NOREF#154  -  []  183.09 58.41 90 top
NOREF#155  -  []  181.55 48.44 0 top
NOREF#156  -  []  58.33 23.5 0 top
NOREF#157  -  []  48.32 16.28 0 top
NOREF#158  -  []  43.62 27.13 90 top
NOREF#159  -  []  183.13 48.69 90 top
NOREF#160  -  []  127.69 74.59 90 top
NOREF#161  -  []  23.43 98.41 90 top
NOREF#162  -  []  181.96 92.89 0 top
NOREF#163  -  []  154.55 142.91 0 top
NOREF#164  -  []  -342.6 224.22 0 top
NOREF#165  -  []  124.54 143.19 0 top
NOREF#166  -  []  133.99 36.59 90 top
NOREF#167  -  []  91.35 127.27 90 top
NOREF#168  -  []  70.09 21.22 90 top
NOREF#169  -  []  53.46 137.47 90 top
NOREF#170  -  []  84.42 118.16 0 top
NOREF#171  -  []  183.26 76.17 90 top
NOREF#172  -  []  30.46 132.29 0 top
NOREF#173  -  []  49 12.38 0 top
NOREF#174  -  []  101.44 137.47 0 top
NOREF#175  -  []  214.26 -32.31 0 top
NOREF#176  -  []  69.46 137.47 90 top
NOREF#177  -  []  158.48 137.55 0 top
NOREF#178  -  []  48.16 16.85 0 top
NOREF#179  -  []  110.83 93.07 0 top
NOREF#180  -  []  164.47 91.99 90 top
NOREF#181  -  []  192.38 2.46 0 top
NOREF#182  -  []  65.24 21 0 top
NOREF#183  -  []  71.42 140.8 0 top
NOREF#184  -  []  157.48 137.95 0 top
NOREF#185  -  []  76.55 143.19 0 top
NOREF#186  -  []  135.57 38.14 90 top
NOREF#187  -  []  11.81 4.38 0 top
NOREF#188  -  []  112.87 81.81 0 top
NOREF#189  -  []  233.59 -50.28 0 top
NOREF#190  -  []  48.8 12.78 0 top
NOREF#191  -  []  135.59 36.59 0 top
NOREF#192  -  []  67.26 20.61 0 top
NOREF#193  -  []  183.09 57.21 90 top
NOREF#194  -  []  77.45 137.47 90 top
NOREF#195  -  []  42.91 64.24 90 top
NOREF#196  -  []  179.72 56.96 0 top
NOREF#197  -  []  29.46 137.47 90 top
NOREF#198  -  []  44.06 132.29 0 top
NOREF#199  -  []  93.18 57.46 90 top
NOREF#200  -  []  63.51 55.88 0 top
NOREF#201  -  []  11.77 35.87 0 top
NOREF#202  -  []  41.36 63.74 0 top
NOREF#203  -  []  108.6 61.07 90 top
NOREF#204  -  []  102.44 132.29 0 top
NOREF#205  -  []  134.19 19 0 top
NOREF#206  -  []  34.46 61.2 90 top
NOREF#207  -  []  59.83 22 90 top
NOREF#208  -  []  183.49 74.72 90 top
NOREF#209  -  []  124.18 71.25 90 top
NOREF#210  -  []  65.03 21.21 0 top
NOREF#211  -  []  30.94 17.52 90 top
NOREF#212  -  []  57.96 23.86 0 top
NOREF#213  -  []  44.37 11.82 90 top
NOREF#214  -  []  28.29 25.98 0 top
NOREF#215  -  []  116.88 31.43 90 top
NOREF#216  -  []  58.9 100.06 0 top
NOREF#217  -  []  48.1 16.22 90 top
NOREF#218  -  []  50.21 12.99 0 top
NOREF#219  -  []  115.34 127.27 90 top
NOREF#220  -  []  145.47 89.71 0 top
NOREF#221  -  []  157.26 45.06 0 top
NOREF#222  -  []  125.44 137.47 90 top
NOREF#223  -  []  51.53 24.68 0 top
NOREF#224  -  []  112.43 93.07 90 top
NOREF#225  -  []  101.44 137.47 90 top
NOREF#226  -  []  16.36 145.1 90 top
NOREF#227  -  []  177.19 148.2 0 top
NOREF#228  -  []  68.06 132.29 0 top
NOREF#229  -  []  96.41 153.05 0 top
NOREF#230  -  []  54.86 129.78 0 top
NOREF#231  -  []  78.45 132.29 0 top
NOREF#232  -  []  13.35 35.42 90 top
NOREF#233  -  []  179.02 100.24 0 top
NOREF#234  -  []  21.43 98.71 90 top
NOREF#235  -  []  56.92 103.13 0 top
NOREF#236  -  []  174.74 137.65 90 top
NOREF#237  -  []  155.08 137.96 0 top
NOREF#238  -  []  46.03 12.43 0 top
NOREF#239  -  []  16.36 150.1 0 top
NOREF#240  -  []  135.14 36.73 0 top
NOREF#241  -  []  69.46 137.47 90 top
NOREF#242  -  []  59.83 22 90 top
NOREF#243  -  []  17.19 -1.13 90 top
NOREF#244  -  []  125.44 137.47 90 top
NOREF#245  -  []  65.45 19.99 90 top
NOREF#246  -  []  174.39 147.8 0 top
NOREF#247  -  []  89.39 86.34 0 top
NOREF#248  -  []  9.91 1.7 0 top
NOREF#249  -  []  23.03 100.21 0 top
NOREF#250  -  []  192.43 -1.89 90 top
NOREF#251  -  []  132.99 88.98 0 top
NOREF#252  -  []  31.79 19.57 0 top
NOREF#253  -  []  126.84 129.78 0 top
NOREF#254  -  []  13.21 48.09 0 top
NOREF#255  -  []  144.47 91.99 0 top
NOREF#256  -  []  112.68 94.65 90 top
NOREF#257  -  []  139.64 129.78 0 top
NOREF#258  -  []  156.08 137.56 0 top
NOREF#259  -  []  14.54 9.07 0 top
NOREF#260  -  []  101.44 137.47 90 top
NOREF#261  -  []  115.93 107.54 90 top
NOREF#262  -  []  102.84 129.78 90 top
NOREF#263  -  []  115.95 62.2 90 top
NOREF#264  -  []  93.45 137.47 90 top
NOREF#265  -  []  133.14 84.98 90 top
NOREF#266  -  []  13.43 48.34 0 top
NOREF#267  -  []  95.53 107.57 0 top
NOREF#268  -  []  191.33 8.66 0 top
NOREF#269  -  []  104.69 47.02 0 top
NOREF#270  -  []  181.91 74.97 0 top
NOREF#271  -  []  194.83 2.86 0 top
NOREF#272  -  []  163.33 127.27 90 top
NOREF#273  -  []  57.86 35.42 0 top
NOREF#274  -  []  42.15 105.66 90 top
NOREF#275  -  []  130.35 117.14 270 top
NOREF#276  -  []  35.95 60.41 90 top
NOREF#277  -  []  9.04 4.62 0 top
NOREF#278  -  []  116.72 31.78 0 top
NOREF#279  -  []  89.82 60.28 0 top
NOREF#280  -  []  16.06 152.25 0 top
NOREF#281  -  []  29.46 137.47 90 top
NOREF#282  -  []  133.14 84.98 0 top
NOREF#283  -  []  93.18 60.6 0 top
NOREF#284  -  []  133.57 18.82 0 top
NOREF#285  -  []  117.44 137.47 90 top
NOREF#286  -  []  166.71 129.97 0 top
NOREF#287  -  []  160.13 137.16 0 top
NOREF#288  -  []  180.6 101.69 90 top
NOREF#289  -  []  166.3 143.67 90 top
NOREF#290  -  []  28.59 25.69 0 top
NOREF#291  -  []  141.44 137.47 90 top
NOREF#292  -  []  54.46 132.29 90 top
NOREF#293  -  []  21.28 98.26 90 top
NOREF#294  -  []  122.31 112.61 0 top
NOREF#295  -  []  13.43 49.54 90 top
NOREF#296  -  []  117.44 137.47 90 top
NOREF#297  -  []  14.74 8.67 90 top
NOREF#298  -  []  101.44 137.47 90 top
NOREF#299  -  []  157.68 137.55 0 top
NOREF#300  -  []  156.47 98.19 0 top
NOREF#301  -  []  155.28 137.56 0 top
NOREF#302  -  []  114.33 107.57 90 top
NOREF#303  -  []  13.43 48.34 90 top
NOREF#304  -  []  41.36 63.74 90 top
NOREF#305  -  []  52.56 143.19 0 top
NOREF#306  -  []  68.47 21.22 0 top
NOREF#307  -  []  57.86 32.48 90 top
NOREF#308  -  []  90.66 108.36 90 top
NOREF#309  -  []  116.58 31.73 0 top
NOREF#310  -  []  59.73 35.15 0 top
NOREF#311  -  []  91.65 129.78 0 top
NOREF#312  -  []  13.76 4.38 0 top
NOREF#313  -  []  43.66 129.78 0 top
NOREF#314  -  []  118.13 31.76 0 top
NOREF#315  -  []  53.46 137.47 0 top
NOREF#316  -  []  22.23 100.21 0 top
NOREF#317  -  []  180.82 100.24 90 top
NOREF#318  -  []  126.44 132.29 0 top
NOREF#319  -  []  110.83 93.07 0 top
NOREF#320  -  []  151.81 143.67 90 top
NOREF#321  -  []  163.47 89.71 90 top
NOREF#322  -  []  175.59 137.7 0 top
NOREF#323  -  []  15.63 59.27 0 top
NOREF#324  -  []  154.87 136.95 90 top
NOREF#325  -  []  125.44 137.47 90 top
NOREF#326  -  []  30.88 24.41 90 top
NOREF#327  -  []  40.3 106.61 90 top
NOREF#328  -  []  28.56 143.19 0 top
NOREF#329  -  []  165.15 20.1 0 top
NOREF#330  -  []  43.2 105.56 90 top
NOREF#331  -  []  16.06 142.95 90 top
NOREF#332  -  []  65.44 20.6 90 top
NOREF#333  -  []  78.85 129.78 0 top
NOREF#334  -  []  218.95 64.94 0 top
NOREF#335  -  []  -0.27 -0.1 0 top
NOREF#336  -  []  30.84 19.67 0 top
NOREF#337  -  []  164.53 19.92 90 top
NOREF#338  -  []  126.84 129.78 90 top
NOREF#339  -  []  43.52 25.38 90 top
NOREF#340  -  []  67.86 20.21 0 top
NOREF#341  -  []  114.31 108.36 90 top
NOREF#342  -  []  30.46 132.29 90 top
NOREF#343  -  []  94.73 107.57 0 top
NOREF#344  -  []  30.86 129.78 0 top
NOREF#345  -  []  100.54 143.19 0 top
NOREF#346  -  []  120.41 153.05 0 top
NOREF#347  -  []  122.31 59.27 0 top
NOREF#348  -  []  174.39 138.3 90 top
NOREF#349  -  []  51.83 12.99 90 top
NOREF#350  -  []  131.94 88.43 0 top
NOREF#351  -  []  56.92 99.83 90 top
NOREF#352  -  []  141.44 137.47 90 top
NOREF#353  -  []  54.86 129.78 90 top
NOREF#354  -  []  159.92 136.95 90 top
NOREF#355  -  []  43.62 25.93 90 top
NOREF#356  -  []  53.46 137.47 90 top
NOREF#357  -  []  67.06 21.01 0 top
NOREF#358  -  []  21.28 100.36 0 top
NOREF#359  -  []  93.45 137.47 90 top
NOREF#360  -  []  21.43 99.91 0 top
NOREF#361  -  []  48.16 16.85 90 top
NOREF#362  -  []  43.95 13.04 0 top
NOREF#363  -  []  16.71 -1.08 90 top
NOREF#364  -  []  182 129.97 90 top
NOREF#365  -  []  60.19 21.63 90 top
NOREF#366  -  []  175.59 137.7 0 top
NOREF#367  -  []  164.53 19.92 0 top
NOREF#368  -  []  139.34 127.27 90 top
NOREF#369  -  []  156.47 98.19 90 top
NOREF#370  -  []  183.54 92.64 90 top
NOREF#371  -  []  160.13 137.16 90 top
NOREF#372  -  []  157.74 47.86 0 top
NOREF#373  -  []  47.43 140.8 0 top
NOREF#374  -  []  165.15 20.1 90 top
NOREF#375  -  []  48.86 13.04 90 top
NOREF#376  -  []  71.09 107.57 0 top
NOREF#377  -  []  11.11 3.9 0 top
NOREF#378  -  []  30.84 16.97 90 top
NOREF#379  -  []  153.65 138.57 0 top
NOREF#380  -  []  104.07 40.85 180 bottom
NOREF#381  -  []  125.21 72.82 90 bottom
NOREF#382  -  []  119.84 102.43 180 bottom
NOREF#383  -  []  51.28 53.12 180 bottom
NOREF#384  -  []  88.12 95.12 180 bottom
NOREF#385  -  []  105.88 47.02 180 bottom
Q1  NX3008NBKW,115  [SC70_3]  25.79 21.44 0 top
Q2  NX3008NBKW,115  [SC70_3]  49.93 23.66 0 top
Q5  NX3008NBKW,115  [SC70_3]  164.48 134.15 0 top
Q6  AO7401  [SC70_3]  185.47 22.06 270 top
Q7  NX3008NBKW,115  [SC70_3]  182.05 19.08 90 top
Q8  AON7405  [DFN3P3X3P3_8L_EX]  58.57 101.48 90 bottom
Q10  NX3008NBKW,115  [SC70_3]  53.41 104.69 90 bottom
Q11  NX3008NBKW,115  [SC70_3]  21.32 50.55 180 bottom
Q12  NX3008NBKW,115  [SC70_3]  19.24 55.47 0 bottom
Q13  NX3008NBKW,115  [SC70_3]  133.68 78.29 270 bottom
Q14  AON7405  [DFN3P3X3P3_8L_EX]  126.04 76.24 270 bottom
Q15  NX3008NBKW,115  [SC70_3]  136.84 75.43 0 bottom
Q16  AO7401  [SC70_3]  176.71 123.24 180 top
Q17  NX3008NBKW,115  [SC70_3]  179.66 123.35 0 top
R1  0  [RC0402_25]  168.68 140.44 180 top
R2  10K  [0402_CC]  25.54 18.18 180 top
R4  10K  [0402_CC]  129.73 83.23 0 bottom
R5  47K  [0603_CC]  71.41 33.07 270 top
R7  10K  [0402_CC]  176.6 102.65 0 top
R8  10K  [0402_CC]  176.57 101.57 0 top
R9  10K  [0402_CC]  176.57 100.47 0 top
R10  10K  [0402_CC]  176.57 99.37 0 top
R11  10K  [0402_CC]  182.64 102.57 180 top
R12  10K  [0402_CC]  182.63 101.51 180 top
R13  10K  [0402_CC]  182.61 100.43 180 top
R14  10K  [0402_CC]  182.61 99.35 180 top
R15  10K  [0402_CC]  179.79 104.22 270 top
R16  10K  [0402_CC]  110.01 97.12 270 bottom
R17  10K  [0402_CC]  111.18 97.13 270 bottom
R18  10K  [0402_CC]  112.78 97.13 270 bottom
R19  10K  [0402_CC]  113.97 97.14 270 bottom
R20  10K  [0402_CC]  109.94 91 90 bottom
R21  10K  [0402_CC]  111.15 91.01 90 bottom
R22  10K  [0402_CC]  112.65 91.01 90 bottom
R23  10K  [0402_CC]  113.83 91.01 90 bottom
R24  10K  [0402_CC]  39.3 67.51 270 bottom
R25  0  [0402_CC]  84.71 135.01 270 bottom
R26  0  [0402_CC]  87.5 126.06 270 top
R27  10K  [0402_CC]  108.83 93.75 0 bottom
R28  0  [0402_CC]  60.28 135.11 270 bottom
R29  0  [0402_CC]  61.34 135.1 90 bottom
R30  0  [RC0402_25]  137.34 86.05 180 bottom
R31  0  [RC0402_25]  149.65 86.86 270 bottom
R32  0  [RC0402_25]  148.61 86.89 270 bottom
R33  1K  [0402_CC]  136.32 80.26 180 bottom
R34  1M  [0402_CC]  136.04 78.56 270 bottom
R35  62.0  [0603_CC]  133.57 74.75 0 bottom
R36  1K  [0402_CC]  133.91 80.3 0 bottom
R37  1K  [0402_CC]  47.13 103.74 180 bottom
R38  10K  [0402_CC]  47.41 14.5 90 bottom
R39  0  [RC0402_25]  23.95 66.2 0 bottom
R40  0  [0402_CC]  50.32 19.73 90 top
R41  2.2K  [0402_CC]  129.73 84.3 0 bottom
R42  100K  [0402_CC]  25.41 24.04 0 top
R43  100K  [0402_CC]  25.42 26.2 180 top
R44  100K  [0402_CC]  29.09 22.76 270 top
R45  100K  [0402_CC]  25.54 19.27 0 top
R46  1.2M  [0402_CC]  70.38 39.77 270 top
R47  1M  [0402_CC]  69.28 33.58 90 top
R48  1K  [0402_CC]  67.06 33.61 90 top
R49  47K  [0402_CC]  41.46 17.27 180 top
R50  100K  [0402_CC]  39.57 18.79 0 top
R51  324K  [0402_CC]  68.19 33.58 270 top
R52  249K  [0402_CC]  69.28 39.77 90 top
R53  0  [RC0805_OV]  50.45 32.09 180 bottom
R54  0  [RC0805_OV]  50.44 29.92 180 bottom
R55  0  [0402_CC]  62.56 35.49 180 top
R56  100K  [0402_CC]  60.09 30.06 90 top
R57  100K  [0402_CC]  62.57 33.66 180 top
R58  0  [0402_CC]  64.75 31.47 0 top
R59  0  [0402_CC]  64.76 32.59 0 top
R60  10K  [0402_CC]  40.2 27.34 0 top
R61  0  [0402_CC]  62.54 31.48 180 top
R62  0  [0402_CC]  62.55 32.58 180 top
R63  0  [0402_CC]  41.83 27.35 180 top
R64  10K  [0402_CC]  49.91 26.11 270 top
R65  1M  [0402_CC]  50.99 26.09 90 top
R66  1K  [0402_CC]  82.18 113.31 270 top
R67  51K  [0402_CC]  56.4 23.64 0 top
R68  10K  [0402_CC]  58.9 25.48 270 top
R70  0  [0402_CC]  108.79 26.27 0 top
R71  0  [0402_CC]  104.94 33.63 90 top
R72  0  [0402_CC]  103.84 33.65 90 top
R73  0  [0402_CC]  102.78 33.63 90 top
R74  510  [0402_CC]  108.18 20.02 90 top
R75  0  [0402_CC]  106.02 33.63 90 top
R76  0  [0402_CC]  101.7 33.63 90 top
R77  0  [0402_CC]  98.45 33.63 90 top
R78  510  [0402_CC]  95.85 19.96 90 top
R79  0  [RC0402_25]  106.58 26.35 0 top
R80  0  [RC0402_25]  106.61 27.7 0 top
R81  2.49K  [0402_CC]  97 23.99 270 top
R82  1M  [1206_CC]  116.6 16.36 270 top
R83  10K  [0402_CC]  106.71 25.16 0 top
R84  10K  [0402_CC]  95.1 36.91 180 top
R85  1.5K  [0402_CC]  108.77 27.74 0 top
R86  4.7K  [0402_CC]  95.09 35.76 0 top
R87  4.7K  [0402_CC]  95.09 29.2 0 top
R88  4.7K  [0402_CC]  104.75 36.13 270 top
R89  4.7K  [0402_CC]  103.66 36.13 270 top
R90  4.7K  [0402_CC]  107.11 33.63 270 top
R91  4.7K  [0402_CC]  107.1 36.13 90 top
R92  4.7K  [0402_CC]  95.09 34.67 180 top
R93  4.7K  [0402_CC]  95.09 31.34 180 top
R94  4.7K  [0402_CC]  95.09 32.44 180 top
R95  4.7K  [0402_CC]  105.82 36.13 90 top
R96  4.7K  [0402_CC]  102.58 36.14 90 top
R97  4.7K  [0402_CC]  100.61 33.63 90 top
R98  4.7K  [0402_CC]  99.53 33.63 90 top
R99  4.7K  [0402_CC]  108.21 36.15 270 top
R100  1.5K  [0402_CC]  90.28 27.63 0 top
R101  0  [0402_CC]  87.25 36.58 270 top
R102  0  [0402_CC]  87.76 34.34 90 top
R103  0  [0402_CC]  83.92 36.58 90 top
R104  510  [0402_CC]  89.45 19.96 90 top
R105  0  [0402_CC]  82.83 36.58 90 top
R106  0  [0402_CC]  88.99 34.34 90 top
R107  0  [0402_CC]  80.39 34.34 90 top
R108  0  [0402_CC]  79.16 34.34 90 top
R109  510  [0402_CC]  76.64 19.96 90 top
R110  0  [RC0402_25]  87.96 25.64 0 top
R111  0  [RC0402_25]  87.96 27.62 0 top
R112  2.49K  [0402_CC]  77.27 23.1 180 top
R113  10K  [0402_CC]  87.8 23.31 0 top
R114  10K  [0402_CC]  75.83 35.19 180 top
R115  4.7K  [0402_CC]  75.83 34.13 0 top
R116  4.7K  [0402_CC]  75.83 27.71 0 top
R117  4.7K  [0402_CC]  85.01 36.58 270 top
R118  4.7K  [0402_CC]  81.69 36.58 270 top
R119  4.7K  [0402_CC]  78.08 34.34 90 top
R120  4.7K  [0402_CC]  85.31 34.34 270 top
R121  4.7K  [0402_CC]  75.83 33.03 180 top
R122  4.7K  [0402_CC]  75.83 28.81 180 top
R123  4.7K  [0402_CC]  75.83 30.92 180 top
R124  4.7K  [0402_CC]  83.95 34.34 90 top
R125  4.7K  [0402_CC]  82.83 34.35 90 top
R126  4.7K  [0402_CC]  81.62 34.34 90 top
R127  4.7K  [0402_CC]  90.09 34.33 270 top
R128  4.7K  [0402_CC]  86.53 34.34 90 top
R129  0  [0402_CC]  163.27 113.81 270 top
R130  0  [0402_CC]  162.19 113.8 270 top
R131  0  [0402_CC]  155.34 111.94 180 top
R132  0  [0402_CC]  155.33 110.65 180 top
R133  0  [0402_CC]  161.13 113.8 270 top
R134  0  [0402_CC]  160.03 113.8 270 top
R135  0  [0402_CC]  153.46 111.94 180 top
R136  0  [0402_CC]  153.5 110.66 180 top
R137  0  [0402_CC]  155.32 109.32 180 top
R138  0  [0402_CC]  155.32 108.24 180 top
R139  0  [0402_CC]  158.39 113.78 270 top
R140  0  [0402_CC]  157.7 105.24 90 top
R141  0  [0402_CC]  161.38 105.18 90 top
R142  0  [0402_CC]  153.43 91.68 0 top
R144  0  [0402_CC]  157.7 103.44 90 top
R147  0  [0402_CC]  166.27 112.27 180 top
R148  0  [0402_CC]  161.55 110.22 0 bottom
R149  10K  [0402_CC]  157.1 86.88 90 bottom
R152  0  [0402_CC]  147.24 86.88 270 bottom
R153  0  [0402_CC]  146.19 86.88 270 bottom
R154  0  [0402_CC]  184.72 133.72 90 bottom
R155  0  [0402_CC]  179.1 133.73 90 bottom
R156  0  [0402_CC]  178.02 133.76 90 bottom
R157  0  [0402_CC]  176.95 133.77 90 bottom
R158  0  [0402_CC]  186.88 133.74 90 bottom
R159  0  [0402_CC]  185.81 133.74 90 bottom
R160  0  [0402_CC]  61.46 126.12 270 top
R161  0  [0402_CC]  85.35 126.06 270 top
R162  0  [0402_CC]  60.4 126.12 270 top
R163  0  [0402_CC]  84.66 132.52 180 bottom
R164  0  [0402_CC]  84.27 126.06 270 top
R165  0  [0402_CC]  83.2 126.06 90 top
R166  0  [0402_CC]  36.72 126.09 270 top
R167  0  [0402_CC]  35.65 126.09 270 top
R168  0  [0402_CC]  111.1 126.11 270 top
R169  0  [0402_CC]  110.04 126.11 270 top
R170  0  [0402_CC]  132.83 126.06 270 top
R171  0  [0402_CC]  108.97 126.1 270 top
R172  0  [0402_CC]  131.72 126.04 270 top
R173  0  [0402_CC]  107.9 126.1 270 top
R174  27K  [0402_CC]  168.48 134.14 180 top
R175  1.2K  [0402_CC]  162.31 134.63 90 top
R176  47K  [0402_CC]  162.33 132.64 90 top
R177  10K  [0402_CC]  161.51 126.47 0 top
R178  10K  [0402_CC]  161.51 125.26 0 top
R179  1.5K  [0402_CC]  172.29 126.78 180 top
R180  1.5K  [0402_CC]  172.28 125.67 180 top
R181  0  [0402_CC]  163.46 126.46 0 top
R183  0  [0402_CC]  163.46 125.27 0 top
R185  10K  [0402_CC]  172.29 124.58 0 top
R186  100K  [0402_CC]  165.11 131.43 90 top
R187  100K  [0402_CC]  198.11 23.89 270 top
R188  0  [0402_CC]  190.17 34.64 270 top
R189  0  [0402_CC]  197.14 32.95 0 top
R190  10K  [0402_CC]  193.77 21.32 90 top
R191  0  [0402_CC]  193.37 34.64 270 top
R192  0  [0402_CC]  192.3 34.65 270 top
R193  0  [0402_CC]  191.24 34.65 270 top
R194  0  [0402_CC]  189.12 34.64 270 top
R195  0  [0402_CC]  194.44 34.64 270 top
R196  10K  [0402_CC]  192.68 21.32 270 top
R197  0  [0402_CC]  186.7 31.71 0 top
R198  0  [0402_CC]  186.7 32.79 0 top
R199  0  [0402_CC]  197.17 25.98 0 top
R200  1K  [0402_CC]  199.8 26.44 0 top
R201  1K  [0402_CC]  199.8 29.72 180 top
R202  0  [0402_CC]  186.7 28.25 180 top
R203  0  [0402_CC]  186.7 30.63 180 top
R204  47K  [0402_CC]  182.11 22 90 top
R205  10K  [0402_CC]  181.01 22 270 top
R206  0  [0402_CC]  188.65 23.89 270 top
R207  0  [0402_CC]  186.49 19.08 270 top
R208  0  [0402_CC]  186.7 27.18 180 top
R209  100K  [0402_CC]  185.4 19.08 90 top
R210  62.0  [0603_CC]  131.32 19.64 90 top
R211  62.0  [0603_CC]  138.58 19.63 90 top
R212  10K  [0402_CC]  138.67 23.85 90 top
R214  62.0  [0603_CC]  162.2 20.73 90 top
R215  62.0  [0603_CC]  169.53 20.75 90 top
R216  10K  [0402_CC]  136.53 41.25 270 top
R217  10K  [0402_CC]  135.41 41.26 270 top
R218  10K  [0402_CC]  137.78 35.14 180 top
R221  0  [RC0402_25]  196.01 127.42 180 top
R222  0  [RC0402_25]  196.04 129.97 180 top
R223  10K  [0402_CC]  182.58 78.43 270 top
R224  10K  [0402_CC]  182.94 96.14 270 top
R225  10K  [0402_CC]  182.04 61.08 270 top
R226  10K  [0402_CC]  182.47 52.31 270 top
R230  0  [0402_CC]  12.85 39.13 270 top
R231  0  [0402_CC]  11.78 39.13 270 top
R232  0  [0402_CC]  10.69 39.13 270 top
R233  0  [0402_CC]  9.6 39.13 270 top
R235  1K  [0402_CC]  11.48 33 90 top
R236  10K  [0402_CC]  4.83 19.44 0 top
R237  1K  [0402_CC]  10.33 32.99 90 top
R238  0  [0402_CC]  17.69 29.68 180 top
R240  10K  [0402_CC]  4.84 18.3 0 top
R241  1K  [0402_CC]  4.88 24.97 0 top
R242  1K  [0402_CC]  9.17 32.99 90 top
R243  10K  [0402_CC]  16.4 125.86 0 top
R244  10K  [0402_CC]  16.38 126.96 0 top
R245  10K  [0402_CC]  16.38 131.22 0 top
R246  100  [0402_CC]  23.71 127.31 180 top
R247  0  [0402_CC]  23.74 131.12 0 top
R248  0  [0402_CC]  23.78 132.4 0 top
R251  3.3  [0603_CC]  39.54 60 270 bottom
R252  10K  [0603_CC]  36.9 69.89 270 bottom
R253  499K  [0402_CC]  38.11 57.64 90 bottom
R254  43K  [0402_CC]  39.57 64.37 0 bottom
R256  499  [0402_CC]  39.58 63.24 0 bottom
R258  100K  [0402_CC]  46.37 62.89 180 bottom
R259  100K  [0402_CC]  46.36 63.99 0 bottom
R260  5.6K  [0402_CC]  39.57 65.48 180 bottom
R261  22K  [0402_CC]  54.37 100.31 90 bottom
R263  4.7K  [0402_CC]  54.36 102.18 90 bottom
R264  22K  [0402_CC]  51.36 102.17 90 bottom
R265  1K  [0402_CC]  52.46 102.17 90 bottom
R266  100K  [0402_CC]  50.86 105.17 180 bottom
R267  100K  [0402_CC]  44.96 105.93 180 bottom
R268  187K  [0402_CC]  42.92 109.67 0 bottom
R269  10K  [0402_CC]  44.97 107.03 180 bottom
R270  1K  [0402_CC]  4.2 139.77 270 top
R271  1K  [0402_CC]  47.13 104.83 180 bottom
R272  100K  [0402_CC]  47.13 107.03 0 bottom
R273  41.2K  [0402_CC]  44.83 110.78 0 bottom
R276  1M  [0402_CC]  26.82 99.72 180 bottom
R278  165K  [0402_CC]  26.83 97.47 0 bottom
R280  71.5K  [0402_CC]  26.82 98.6 0 bottom
R281  1K  [0402_CC]  19.02 98.35 0 bottom
R282  100K  [0402_CC]  19.03 99.45 0 bottom
R283  2.2K  [0402_CC]  4.89 135.34 90 top
R284  2.2K  [0402_CC]  6.36 135.34 90 top
R285  2.2K  [0402_CC]  7.83 135.34 90 top
R286  2.2K  [0402_CC]  9.31 135.34 90 top
R287  100K  [0402_CC]  8.9 124.89 270 top
R288  100K  [0402_CC]  7.63 124.88 270 top
R289  100K  [0402_CC]  6.37 124.89 270 top
R290  100K  [0402_CC]  5.1 124.88 270 top
R291  0  [0402_CC]  30.77 21.6 270 top
R292  0  [0402_CC]  31.86 21.61 270 top
R293  0  [RC0402_25]  178.82 59.69 0 top
R294  0  [RC0402_25]  178.82 58.42 0 top
R295  0  [RC0402_25]  178.82 57.15 0 top
R296  0  [RC0402_25]  178.82 55.88 0 top
R297  0  [RC0402_25]  178.92 49.47 0 top
R298  0  [0402_CC]  82.22 113.05 270 bottom
R299  0  [0402_CC]  81.16 113.05 270 bottom
R300  0  [0402_CC]  82.22 110.44 270 bottom
R301  0  [0402_CC]  81.16 110.44 270 bottom
R302  0  [0402_CC]  57.77 25.48 270 top
R303  0  [0402_CC]  86.43 126.06 270 top
R304  0  [0402_CC]  37.81 126.09 270 top
R305  0  [0402_CC]  38.89 126.09 270 top
R306  0  [0402_CC]  183.91 89.2 270 top
R307  0  [0402_CC]  182.83 89.21 270 top
R308  0  [0402_CC]  181.73 89.2 270 top
R309  0  [RC0805_OV]  85.98 62.97 0 bottom
R310  0  [RC0805_OV]  85.98 60.93 0 bottom
R312  10K  [0402_CC]  120.98 30.89 180 top
R313  2.2K  [RC0402_25]  83.18 112.29 90 bottom
R314  0  [RC0402_25]  129.65 85.43 0 bottom
R315  0  [RC0402_25]  129.65 86.51 0 bottom
R317  0  [RC0402_25]  103.54 65.47 90 top
R318  0  [RC0402_25]  104.49 65.46 90 top
R322  10K  [0402_CC]  120.99 31.94 180 top
R323  10K  [0402_CC]  115.03 31.47 0 top
R327  22  [0402_CC]  14.18 10.82 90 top
